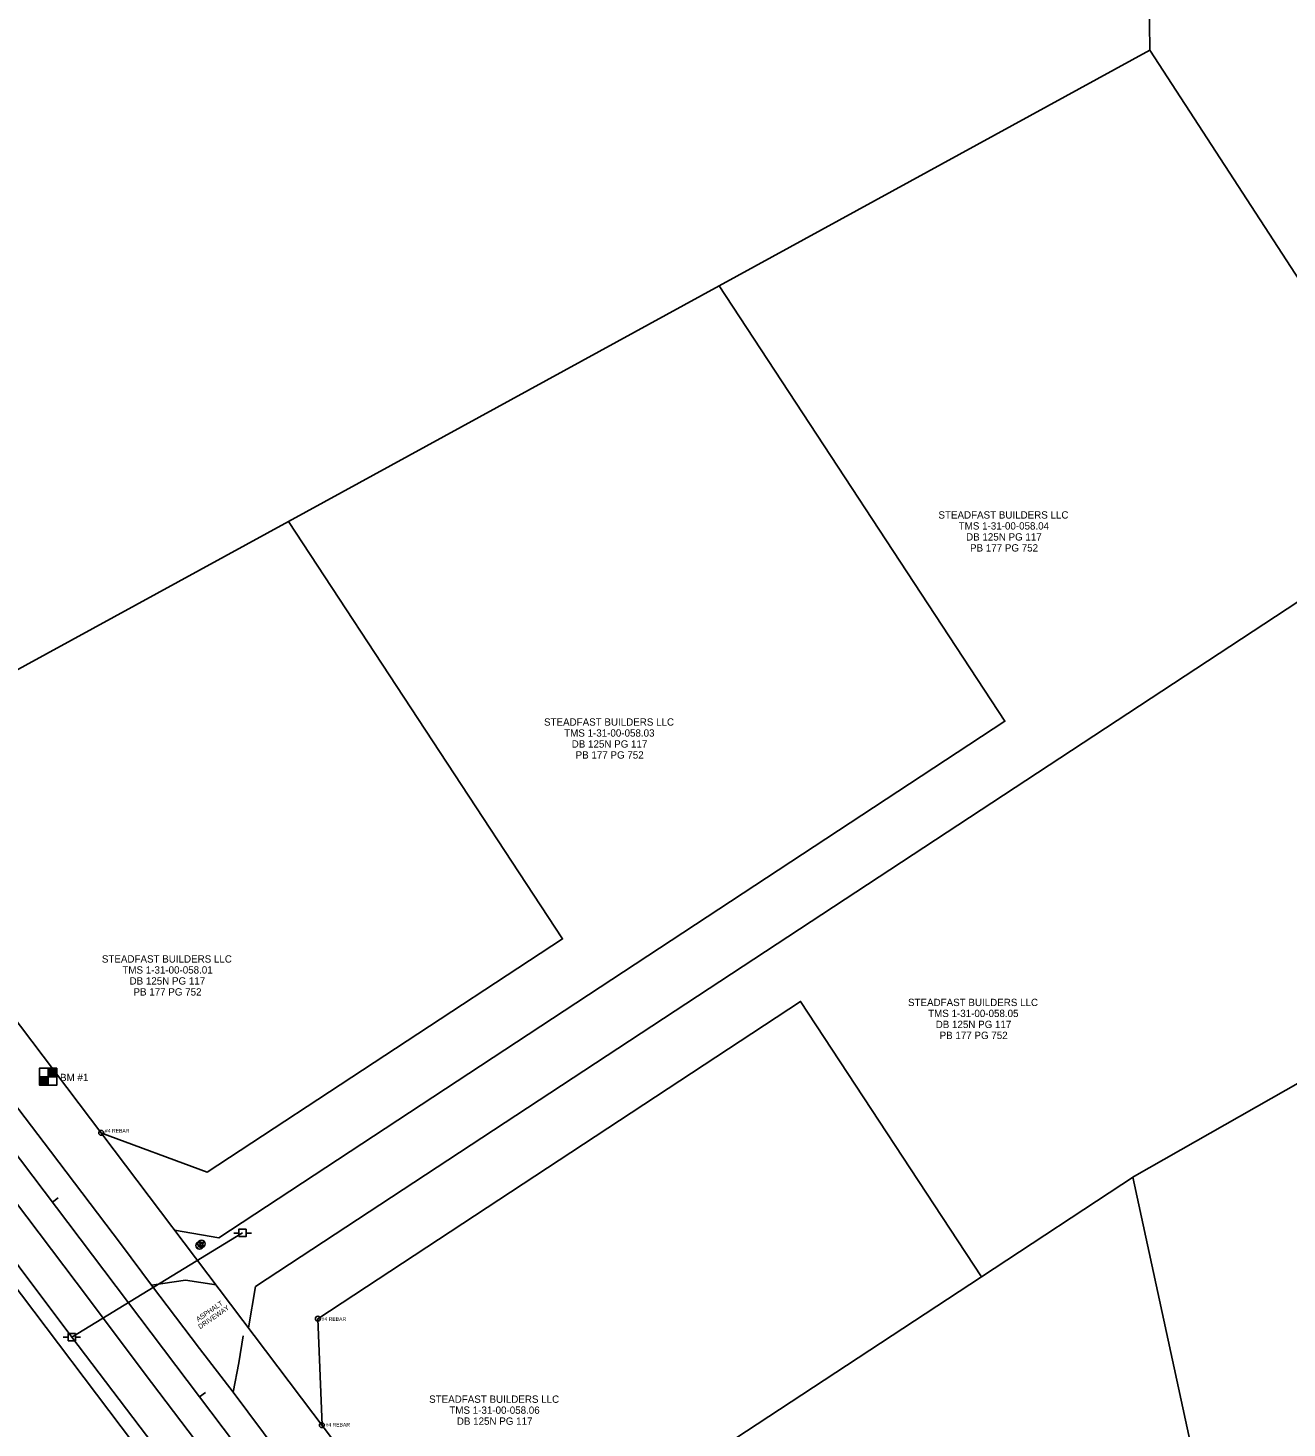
# Model space of a CAD drawing. Extents: x 1642870 to 1644553, y 1183846 to 1185844.
# Drawn here: x 1643707 to 1644223, y 1184728 to 1185301 of the extents above; entities that cross this region are included whole.
import ezdxf

# ---------------------------------------------------------------- set-up
doc = ezdxf.new("R2010")
doc.units = 0
for name, color, linetype in [('RD_EX_DV_Prop', 7, 'Continuous'), ('RD_EX_DV_Prop_txCode', 7, 'Continuous'), ('RD_EX_DV_PropPin', 7, 'Continuous'), ('RD_EX_DV_TX_Prop', 7, 'Continuous'), ('RD_EX_Road', 7, 'Continuous'), ('RD_EX_RW', 7, 'Continuous'), ('RD_EX_UT', 7, 'Continuous'), ('RD_HC_Cl', 7, 'Continuous'), ('RD_HC_Data_Tic', 7, 'Continuous'), ('RD_HC_Survey', 7, 'Continuous'), ('RD_HC_Survey_txCode', 7, 'Continuous'), ('RD_TX_Misc1', 7, 'Continuous')]:
    doc.layers.add(name, color=color, linetype=linetype)

msp = doc.modelspace()

# ---------------------------------------------------------------- linework, layer by layer
at = {"layer": 'RD_EX_DV_Prop'}
msp.add_line((1644161.63, 1185636.32), (1644167.11, 1185292.24), dxfattribs=at)
for points in [[(1643625.87, 1184996.23), (1643814.06, 1185099.16), (1643990.56, 1185195.67), (1644167.11, 1185292.24)], [(1644167.11, 1185292.24), (1644288.23, 1185105.94), (1644383.88, 1184957.62)], [(1643767.4, 1184808.78), (1643785.52, 1184805.65), (1644107.73, 1185017.29), (1643990.56, 1185195.67)], [(1643797.69, 1184768.73), (1643800.62, 1184785.67), (1644288.23, 1185105.94)], [(1643737.2, 1184848.72), (1643780.86, 1184832.5), (1643926.42, 1184928.11), (1643814.06, 1185099.16)], [(1644383.88, 1184957.62), (1644160.78, 1184830.87), (1644098.09, 1184789.7), (1643886.79, 1184650.9)], [(1643827.86, 1184728.83), (1643826.18, 1184772.52), (1644024.01, 1184902.48), (1644098.09, 1184789.7)], [(1644026.86, 1184465.66), (1644214.86, 1184577.89), (1644160.18, 1184830.48)]]:
    msp.add_lwpolyline(points, dxfattribs=at)
at = {"layer": 'RD_EX_DV_PropPin'}
for centre in [(1643737.39, 1184848.65), (1643826.18, 1184772.52), (1643827.78, 1184728.87)]:
    msp.add_circle(centre, 1, dxfattribs=at)
at = {"layer": 'RD_EX_Road'}
for points in [[(1644073.99, 1184326.12), (1644045.6, 1184366.75), (1644015.16, 1184406.64), (1643998.93, 1184428.49), (1643983.25, 1184449.14), (1643956.67, 1184484.03), (1643908.42, 1184547.11), (1643879.67, 1184585.06), (1643849.7, 1184625.13), (1643820.64, 1184664.16), (1643791.09, 1184702.78), (1643757.99, 1184746.42), (1643727.17, 1184787.53), (1643696.82, 1184827.61), (1643674.57, 1184857.51), (1643649.6, 1184890.04), (1643644.71, 1184897.22), (1643610.96, 1184937.11)], [(1643809.94, 1184717.64), (1643791.44, 1184742.35), (1643777.67, 1184760.32), (1643758.01, 1184786.25), (1643745.63, 1184802.8), (1643716.57, 1184841.11), (1643687.94, 1184878.71)], [(1643758.01, 1184786.25), (1643771.98, 1184788.24), (1643784.54, 1184786.44)], [(1643791.44, 1184742.35), (1643793.81, 1184754.38), (1643795.52, 1184765.5)]]:
    msp.add_lwpolyline(points, dxfattribs=at)
at = {"layer": 'RD_EX_RW'}
for p, q in [((1643225.58, 1185525.31), (1644072.06, 1184405.88)), ((1643193.75, 1185457.98), (1644019.42, 1184366.08))]:
    msp.add_line(p, q, dxfattribs=at)
at = {"layer": 'RD_EX_UT'}
for p, q in [((1643776.28, 1184803.15), (1643778.96, 1184801.78)), ((1643776.59, 1184801.42), (1643778.66, 1184803.53)), ((1643778.47, 1184801.66), (1643777.5, 1184804.28)), ((1643778.47, 1184801.66), (1643779.46, 1184804.25)), ((1643791.71, 1184807.62), (1643793.77, 1184807.62)), ((1643795.27, 1184807.66), (1643795.27, 1184807.66)), ((1643796.77, 1184807.62), (1643798.91, 1184807.62)), ((1643721.72, 1184764.89), (1643723.78, 1184764.89)), ((1643725.28, 1184764.93), (1643725.28, 1184764.93)), ((1643726.78, 1184764.89), (1643728.92, 1184764.89))]:
    msp.add_line(p, q, dxfattribs=at)
for points in [[(1643542.71, 1185007.25), (1643638.46, 1184880.82), (1643725.28, 1184764.93), (1643795.27, 1184807.66)], [(1643725.28, 1184764.93), (1643817.51, 1184643.49), (1643906.91, 1184524.77), (1643917.32, 1184611.5)]]:
    msp.add_lwpolyline(points, dxfattribs=at)
for points in [[(1643793.77, 1184806.16), (1643793.77, 1184809.16), (1643796.77, 1184809.16), (1643796.77, 1184806.16)], [(1643723.78, 1184763.43), (1643723.78, 1184766.43), (1643726.78, 1184766.43), (1643726.78, 1184763.43)]]:
    msp.add_lwpolyline(points, close=True, dxfattribs=at)
for centre in [(1643777.64, 1184802.48), (1643778.47, 1184803.16)]:
    msp.add_circle(centre, 1.5, dxfattribs=at)
at = {"layer": 'RD_HC_Cl'}
msp.add_line((1643229.22, 1185465.79), (1644045.74, 1184385.98), dxfattribs=at)
at = {"layer": 'RD_HC_Data_Tic'}
for p, q in [((1643717.39, 1184820.21), (1643719.78, 1184822.02)), ((1643777.7, 1184740.45), (1643780.1, 1184742.26))]:
    msp.add_line(p, q, dxfattribs=at)
at = {"layer": 'RD_HC_Survey'}
for p, q in [((1643719.18, 1184871.67), (1643712.11, 1184871.67)), ((1643712.11, 1184871.67), (1643712.11, 1184868.14)), ((1643712.16, 1184871.67), (1643712.16, 1184868.14)), ((1643712.21, 1184871.67), (1643712.21, 1184868.14)), ((1643712.26, 1184871.67), (1643712.26, 1184868.14)), ((1643712.31, 1184871.67), (1643712.31, 1184868.14)), ((1643712.36, 1184871.67), (1643712.36, 1184868.14)), ((1643712.41, 1184871.67), (1643712.41, 1184868.14)), ((1643712.46, 1184871.67), (1643712.46, 1184868.14)), ((1643712.51, 1184871.67), (1643712.51, 1184868.14)), ((1643712.56, 1184871.67), (1643712.56, 1184868.14)), ((1643712.61, 1184871.67), (1643712.61, 1184868.14)), ((1643712.66, 1184871.67), (1643712.66, 1184868.14)), ((1643712.71, 1184871.67), (1643712.71, 1184868.14)), ((1643712.76, 1184871.67), (1643712.76, 1184868.14)), ((1643712.81, 1184871.67), (1643712.81, 1184868.14)), ((1643712.86, 1184871.67), (1643712.86, 1184868.14)), ((1643712.91, 1184871.67), (1643712.91, 1184868.14)), ((1643712.96, 1184871.67), (1643712.96, 1184868.14)), ((1643713.01, 1184871.67), (1643713.01, 1184868.14)), ((1643713.06, 1184871.67), (1643713.06, 1184868.14)), ((1643713.11, 1184871.67), (1643713.11, 1184868.14)), ((1643713.16, 1184871.67), (1643713.16, 1184868.14)), ((1643713.21, 1184871.67), (1643713.21, 1184868.14)), ((1643713.26, 1184871.67), (1643713.26, 1184868.14)), ((1643713.31, 1184871.67), (1643713.31, 1184868.14)), ((1643713.36, 1184871.67), (1643713.36, 1184868.14)), ((1643713.41, 1184871.67), (1643713.41, 1184868.14)), ((1643713.46, 1184871.67), (1643713.46, 1184868.14)), ((1643713.51, 1184871.67), (1643713.51, 1184868.14)), ((1643713.56, 1184871.67), (1643713.56, 1184868.14)), ((1643713.61, 1184871.67), (1643713.61, 1184868.14)), ((1643713.66, 1184871.67), (1643713.66, 1184868.14)), ((1643713.71, 1184871.67), (1643713.71, 1184868.14)), ((1643713.76, 1184871.67), (1643713.76, 1184868.14)), ((1643713.81, 1184871.67), (1643713.81, 1184868.14)), ((1643713.86, 1184871.67), (1643713.86, 1184868.14)), ((1643713.91, 1184871.67), (1643713.91, 1184868.14)), ((1643713.96, 1184871.67), (1643713.96, 1184868.14)), ((1643714.01, 1184871.67), (1643714.01, 1184868.14)), ((1643714.06, 1184871.67), (1643714.06, 1184868.14)), ((1643714.11, 1184871.67), (1643714.11, 1184868.14)), ((1643714.16, 1184871.67), (1643714.16, 1184868.14)), ((1643714.21, 1184871.67), (1643714.21, 1184868.14)), ((1643714.26, 1184871.67), (1643714.26, 1184868.14)), ((1643714.31, 1184871.67), (1643714.31, 1184868.14)), ((1643714.36, 1184871.67), (1643714.36, 1184868.14)), ((1643714.41, 1184871.67), (1643714.41, 1184868.14)), ((1643714.46, 1184871.67), (1643714.46, 1184868.14)), ((1643714.51, 1184871.67), (1643714.51, 1184868.14)), ((1643714.56, 1184871.67), (1643714.56, 1184868.14)), ((1643714.61, 1184871.67), (1643714.61, 1184868.14)), ((1643714.66, 1184871.67), (1643714.66, 1184868.14)), ((1643714.71, 1184871.67), (1643714.71, 1184868.14)), ((1643714.76, 1184871.67), (1643714.76, 1184868.14)), ((1643714.81, 1184871.67), (1643714.81, 1184868.14)), ((1643714.86, 1184871.67), (1643714.86, 1184868.14)), ((1643714.91, 1184871.67), (1643714.91, 1184868.14)), ((1643714.96, 1184871.67), (1643714.96, 1184868.14)), ((1643715.01, 1184871.67), (1643715.01, 1184868.14)), ((1643715.06, 1184871.67), (1643715.06, 1184868.14)), ((1643715.11, 1184871.67), (1643715.11, 1184868.14)), ((1643715.16, 1184871.67), (1643715.16, 1184868.14)), ((1643715.21, 1184871.67), (1643715.21, 1184868.14)), ((1643715.26, 1184871.67), (1643715.26, 1184868.14)), ((1643715.31, 1184871.67), (1643715.31, 1184868.14)), ((1643715.36, 1184871.67), (1643715.36, 1184868.14)), ((1643715.41, 1184871.67), (1643715.41, 1184868.14)), ((1643715.46, 1184871.67), (1643715.46, 1184868.14)), ((1643715.51, 1184871.67), (1643715.51, 1184868.14)), ((1643715.56, 1184871.67), (1643715.56, 1184868.14)), ((1643715.61, 1184871.67), (1643715.61, 1184868.14)), ((1643715.65, 1184875.21), (1643715.65, 1184868.14)), ((1643715.68, 1184875.21), (1643715.68, 1184871.67)), ((1643715.73, 1184875.21), (1643715.73, 1184871.67)), ((1643715.78, 1184875.21), (1643715.78, 1184871.67)), ((1643715.83, 1184875.21), (1643715.83, 1184871.67)), ((1643715.88, 1184875.21), (1643715.88, 1184871.67)), ((1643715.93, 1184875.21), (1643715.93, 1184871.67)), ((1643715.98, 1184875.21), (1643715.98, 1184871.67)), ((1643716.03, 1184875.21), (1643716.03, 1184871.67)), ((1643716.08, 1184875.21), (1643716.08, 1184871.67)), ((1643716.13, 1184875.21), (1643716.13, 1184871.67)), ((1643716.18, 1184875.21), (1643716.18, 1184871.67)), ((1643716.23, 1184875.21), (1643716.23, 1184871.67)), ((1643716.28, 1184875.21), (1643716.28, 1184871.67)), ((1643716.33, 1184875.21), (1643716.33, 1184871.67)), ((1643716.38, 1184875.21), (1643716.38, 1184871.67)), ((1643716.43, 1184875.21), (1643716.43, 1184871.67)), ((1643716.48, 1184875.21), (1643716.48, 1184871.67)), ((1643716.53, 1184875.21), (1643716.53, 1184871.67)), ((1643716.58, 1184875.21), (1643716.58, 1184871.67)), ((1643716.63, 1184875.21), (1643716.63, 1184871.67)), ((1643716.68, 1184875.21), (1643716.68, 1184871.67)), ((1643716.73, 1184875.21), (1643716.73, 1184871.67)), ((1643716.78, 1184875.21), (1643716.78, 1184871.67)), ((1643716.83, 1184875.21), (1643716.83, 1184871.67)), ((1643716.88, 1184875.21), (1643716.88, 1184871.67)), ((1643716.93, 1184875.21), (1643716.93, 1184871.67)), ((1643716.98, 1184875.21), (1643716.98, 1184871.67)), ((1643717.03, 1184875.21), (1643717.03, 1184871.67)), ((1643717.08, 1184875.21), (1643717.08, 1184871.67)), ((1643717.13, 1184875.21), (1643717.13, 1184871.67)), ((1643717.18, 1184875.21), (1643717.18, 1184871.67)), ((1643717.23, 1184875.21), (1643717.23, 1184871.67)), ((1643717.28, 1184875.21), (1643717.28, 1184871.67)), ((1643717.33, 1184875.21), (1643717.33, 1184871.67)), ((1643717.38, 1184875.21), (1643717.38, 1184871.67)), ((1643717.43, 1184875.21), (1643717.43, 1184871.67)), ((1643717.48, 1184875.21), (1643717.48, 1184871.67)), ((1643717.53, 1184875.21), (1643717.53, 1184871.67)), ((1643717.58, 1184875.21), (1643717.58, 1184871.67)), ((1643717.63, 1184875.21), (1643717.63, 1184871.67)), ((1643717.68, 1184875.21), (1643717.68, 1184871.67)), ((1643717.73, 1184875.21), (1643717.73, 1184871.67)), ((1643717.78, 1184875.21), (1643717.78, 1184871.67)), ((1643717.83, 1184875.21), (1643717.83, 1184871.67)), ((1643717.88, 1184875.21), (1643717.88, 1184871.67)), ((1643717.93, 1184875.21), (1643717.93, 1184871.67)), ((1643717.98, 1184875.21), (1643717.98, 1184871.67)), ((1643718.03, 1184875.21), (1643718.03, 1184871.67)), ((1643718.08, 1184875.21), (1643718.08, 1184871.67)), ((1643718.13, 1184875.21), (1643718.13, 1184871.67)), ((1643718.18, 1184875.21), (1643718.18, 1184871.67)), ((1643718.23, 1184875.21), (1643718.23, 1184871.67)), ((1643718.28, 1184875.21), (1643718.28, 1184871.67)), ((1643718.33, 1184875.21), (1643718.33, 1184871.67)), ((1643718.38, 1184875.21), (1643718.38, 1184871.67)), ((1643718.43, 1184875.21), (1643718.43, 1184871.67)), ((1643718.48, 1184875.21), (1643718.48, 1184871.67)), ((1643718.53, 1184875.21), (1643718.53, 1184871.67)), ((1643718.58, 1184875.21), (1643718.58, 1184871.67)), ((1643718.63, 1184875.21), (1643718.63, 1184871.67)), ((1643718.68, 1184875.21), (1643718.68, 1184871.67)), ((1643718.73, 1184875.21), (1643718.73, 1184871.67)), ((1643718.78, 1184875.21), (1643718.78, 1184871.67)), ((1643718.83, 1184875.21), (1643718.83, 1184871.67)), ((1643718.88, 1184875.21), (1643718.88, 1184871.67)), ((1643718.93, 1184875.21), (1643718.93, 1184871.67)), ((1643718.98, 1184875.21), (1643718.98, 1184871.67)), ((1643719.03, 1184875.21), (1643719.03, 1184871.67)), ((1643719.08, 1184875.21), (1643719.08, 1184871.67)), ((1643719.13, 1184875.21), (1643719.13, 1184871.67))]:
    msp.add_line(p, q, dxfattribs=at)
msp.add_lwpolyline([(1643719.18, 1184875.21), (1643712.11, 1184875.21), (1643712.11, 1184868.14), (1643719.18, 1184868.14)], close=True, dxfattribs=at)

# ---------------------------------------------------------------- texts
at = {"layer": 'RD_EX_DV_Prop_txCode'}
for p in [(1643738.92, 1184848.77), (1643827.72, 1184771.62), (1643829.3, 1184728.34)]:
    msp.add_text('#4 REBAR', height=1.5, dxfattribs=at).set_placement(p)
at = {"layer": 'RD_EX_DV_TX_Prop'}
for s, p in [('STEADFAST BUILDERS LLC', (1644080.47, 1185100.33)), ('TMS 1-31-00-058.04', (1644088.78, 1185095.83)), ('DB 125N PG 117', (1644091.81, 1185091.33)), ('PB 177 PG 752', (1644093.42, 1185086.83)), ('STEADFAST BUILDERS LLC', (1643918.84, 1185015.49)), ('TMS 1-31-00-058.03', (1643927.1, 1185010.99)), ('DB 125N PG 117', (1643930.19, 1185006.49)), ('PB 177 PG 752', (1643931.8, 1185001.99)), ('STEADFAST BUILDERS LLC', (1643737.65, 1184918.41)), ('TMS 1-31-00-058.01', (1643746.05, 1184913.91)), ('DB 125N PG 117', (1643749, 1184909.41)), ('PB 177 PG 752', (1643750.61, 1184904.91)), ('STEADFAST BUILDERS LLC', (1644068, 1184900.6)), ('TMS 1-31-00-058.05', (1644076.26, 1184896.1)), ('DB 125N PG 117', (1644079.35, 1184891.6)), ('PB 177 PG 752', (1644080.96, 1184887.1)), ('STEADFAST BUILDERS LLC', (1643871.76, 1184738.05)), ('TMS 1-31-00-058.06', (1643880.05, 1184733.55)), ('DB 125N PG 117', (1643883.11, 1184729.05))]:
    msp.add_text(s, height=3, dxfattribs=at).set_placement(p)
at = {"layer": 'RD_HC_Survey_txCode'}
msp.add_text('BM #1', height=3, dxfattribs=at).set_placement((1643720.51, 1184869.86))
at = {"layer": 'RD_TX_Misc1'}
for s, p in [('ASPHALT', (1643777.09, 1184771.21)), ('DRIVEWAY', (1643777.95, 1184768.17))]:
    msp.add_text(s, height=2, rotation=34.52966, dxfattribs=at).set_placement(p)

doc.saveas('drawing.dxf')
